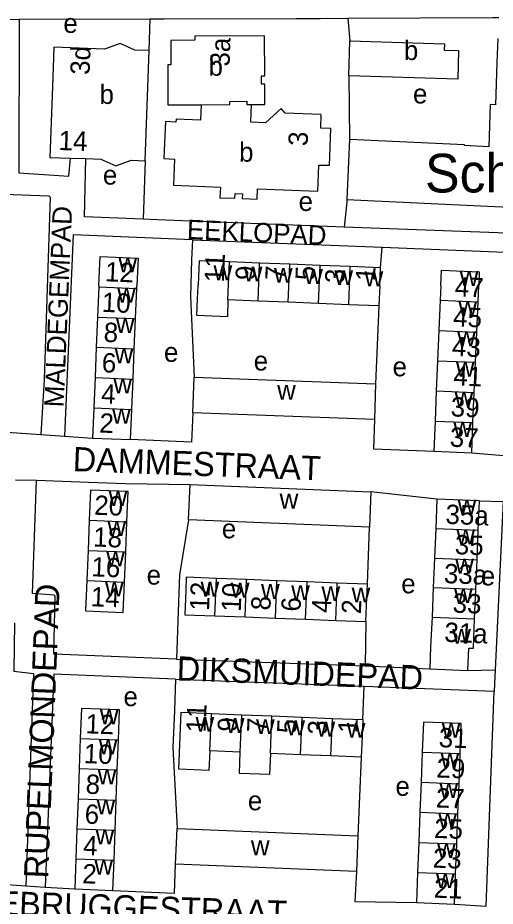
# Model space of a CAD drawing. Extents: x 159675 to 162108, y 386471 to 388472.
# Drawn here: x 161157.6 to 161256.3, y 387621.6 to 387805.3 of the extents above; entities that cross this region are included whole.
import ezdxf

# ---------------------------------------------------------------- set-up
doc = ezdxf.new("R2010")
doc.units = 0
for name, color, linetype in [('BLT_Basislijn', 7, 'Continuous'), ('BLT_Bebouwing', 7, 'Continuous'), ('BLT_Bebouwing_beschrifting', 7, 'Continuous'), ('BLT_Centroide', 7, 'Continuous'), ('BLT_Huisnummer', 7, 'Continuous'), ('BLT_Huisnummer_ tussenligend', 7, 'Continuous'), ('BLT_Huisnummer_reeks', 7, 'Continuous'), ('BLT_Onderverdeling_panden', 7, 'Continuous'), ('BLT_Straatnaam', 7, 'Continuous'), ('BLT_Straatnaam_verkleind', 7, 'Continuous')]:
    doc.layers.add(name, color=color, linetype=linetype)

msp = doc.modelspace()

# ---------------------------------------------------------------- linework, layer by layer
at = {"layer": 'BLT_Basislijn'}
for p, q in [((161157.89, 387804.95), (161152.15, 387804.93)), ((161184.98, 387805.06), (161157.89, 387804.95)), ((161184.77, 387798.54), (161184.98, 387805.06)), ((161225.84, 387805.18), (161220.1, 387805.13)), ((161225.84, 387805.18), (161226.26, 387800.55)), ((161226.06, 387793.34), (161226.2, 387780.16)), ((161183.97, 387775.78), (161183.53, 387763.68)), ((161269.96, 387760.39), (161225.06, 387762.07)), ((161193.74, 387759.43), (161232.92, 387757.9)), ((161232.56, 387753.63), (161232.92, 387757.9)), ((161232.92, 387757.9), (161259.97, 387756.83)), ((161232.25, 387745.77), (161231.57, 387729.68)), ((161153.1, 387719.82), (161162.41, 387719.17)), ((161162.41, 387719.17), (161167.29, 387718.83)), ((161167.29, 387718.83), (161173.07, 387718.43)), ((161157.17, 387709.83), (161161.52, 387709.74)), ((161244.23, 387705.84), (161230.61, 387707.33)), ((161229.88, 387688.22), (161230.33, 387700.04)), ((161229.58, 387680.49), (161229.39, 387671.34)), ((161190.41, 387672.72), (161229.39, 387671.34)), ((161229.39, 387671.34), (161242.75, 387670.73)), ((161250.62, 387670.41), (161256.25, 387670.49)), ((161256.25, 387670.49), (161256.06, 387666.14)), ((161190.19, 387668.6), (161229.18, 387667.17)), ((161228.9, 387660.23), (161229.18, 387667.17)), ((161229.18, 387667.17), (161256.06, 387666.14)), ((161228.58, 387652.46), (161227.88, 387636.23)), ((161149.47, 387626.55), (161159.31, 387625.89)), ((161159.31, 387625.89), (161163.27, 387625.62)), ((161163.27, 387625.62), (161169.41, 387625.21))]:
    msp.add_line(p, q, dxfattribs=at)
for points in [[(161157.89, 387804.95), (161157.83, 387773.27), (161168.2, 387772.6), (161168.51, 387776.32)], [(161220.1, 387805.13), (161219.63, 387805.13), (161215.14, 387805.11), (161187.9, 387805.07), (161184.98, 387805.06)], [(161257.04, 387805.3), (161255.77, 387805.3), (161225.84, 387805.18)], [(161183.53, 387763.68), (161171.41, 387764.2), (161171.68, 387776.21)], [(161125.28, 387769.96), (161164.04, 387768.55), (161164.3, 387768.27), (161163.08, 387730.58), (161162.41, 387719.17)], [(161225.63, 387767.73), (161225.6, 387767.23), (161225.06, 387762.07)], [(161225.06, 387762.07), (161186.45, 387763.55), (161183.53, 387763.68)], [(161193.74, 387759.43), (161169.09, 387760.48), (161167.29, 387718.83)], [(161193.74, 387759.43), (161193.54, 387755.28), (161193.3, 387747.64), (161194.06, 387731.05)], [(161251.43, 387715.39), (161258.08, 387714.85), (161258.61, 387722.94), (161259.97, 387756.83)], [(161193.77, 387723.68), (161193.51, 387717.61), (161180.92, 387718.11)], [(161231.32, 387722.27), (161231.13, 387716.18), (161243.57, 387715.72)], [(161190.41, 387672.72), (161165.11, 387673.79), (161165.36, 387685.72), (161165.17, 387685.99), (161160.64, 387686.31), (161161.52, 387709.74)], [(161161.52, 387709.74), (161172.26, 387709.3), (161179.86, 387709.07), (161193.23, 387708.84)], [(161253.03, 387705.48), (161257.9, 387705.31), (161256.25, 387670.49)], [(161192.92, 387701.54), (161191.03, 387690.16), (161190.75, 387682.56), (161190.41, 387672.72)], [(161156.94, 387680.23), (161156.8, 387670.24), (161160.89, 387669.76), (161159.31, 387625.89)], [(161190.19, 387668.6), (161165.11, 387669.62), (161163.27, 387625.62)], [(161190.19, 387668.6), (161190.02, 387662.14), (161189.65, 387654.43), (161190.53, 387637.75)], [(161247.84, 387622.1), (161254.42, 387621.69), (161256.06, 387666.14)], [(161177.29, 387624.92), (161189.99, 387624.37), (161190.24, 387630.36)], [(161227.59, 387628.8), (161227.29, 387622.6), (161239.99, 387622.41)]]:
    msp.add_lwpolyline(points, dxfattribs=at)
at = {"layer": 'BLT_Bebouwing'}
for p, q in [((161183.97, 387775.78), (161184.77, 387798.54)), ((161195.53, 387787.36), (161195.4, 387784.14)), ((161168.51, 387776.32), (161171.68, 387776.21)), ((161207.59, 387754.62), (161201.35, 387754.86)), ((161213.83, 387754.37), (161207.59, 387754.62)), ((161220.08, 387754.12), (161213.83, 387754.37)), ((161226.32, 387753.88), (161220.08, 387754.12)), ((161232.56, 387753.63), (161226.32, 387753.88)), ((161232.41, 387750), (161232.56, 387753.63)), ((161174.37, 387749.72), (161174.11, 387743.46)), ((161174.38, 387750), (161174.37, 387749.72)), ((161181.97, 387743.13), (161182.23, 387749.39)), ((161182.23, 387749.39), (161182.25, 387750)), ((161245.02, 387750), (161244.89, 387746.92)), ((161252.74, 387746.59), (161252.88, 387750)), ((161207.28, 387746.75), (161201.04, 387747)), ((161213.52, 387746.51), (161207.28, 387746.75)), ((161219.77, 387746.26), (161213.52, 387746.51)), ((161226.01, 387746.01), (161219.77, 387746.26)), ((161232.25, 387745.77), (161226.01, 387746.01)), ((161244.89, 387746.92), (161244.62, 387740.68)), ((161252.48, 387740.35), (161252.74, 387746.59)), ((161174.11, 387743.46), (161173.85, 387737.2)), ((161181.71, 387736.88), (161181.97, 387743.13)), ((161244.62, 387740.68), (161244.36, 387734.44)), ((161252.21, 387734.11), (161252.48, 387740.35)), ((161173.85, 387737.2), (161173.59, 387730.95)), ((161181.45, 387730.62), (161181.71, 387736.88)), ((161244.36, 387734.44), (161244.1, 387728.2)), ((161251.95, 387727.87), (161252.21, 387734.11)), ((161173.59, 387730.95), (161173.33, 387724.69)), ((161181.18, 387724.36), (161181.45, 387730.62)), ((161193.77, 387723.68), (161194.06, 387731.05)), ((161194.06, 387731.05), (161231.57, 387729.68)), ((161231.57, 387729.68), (161231.32, 387722.27)), ((161244.1, 387728.2), (161243.84, 387721.96)), ((161251.69, 387721.63), (161251.95, 387727.87)), ((161173.33, 387724.69), (161173.07, 387718.43)), ((161180.92, 387718.11), (161181.18, 387724.36)), ((161231.32, 387722.27), (161193.77, 387723.68)), ((161243.84, 387721.96), (161243.57, 387715.72)), ((161251.43, 387715.39), (161251.69, 387721.63)), ((161173.07, 387718.43), (161180.92, 387718.11)), ((161243.57, 387715.72), (161251.43, 387715.39)), ((161192.92, 387701.54), (161193.23, 387708.84)), ((161193.23, 387708.84), (161230.61, 387707.33)), ((161230.61, 387707.33), (161230.33, 387700.04)), ((161244.23, 387705.84), (161243.99, 387699.74)), ((161253.03, 387705.48), (161244.23, 387705.84)), ((161252.78, 387699.38), (161253.03, 387705.48)), ((161172.39, 387701.45), (161172.14, 387695.21)), ((161179.93, 387694.9), (161180.18, 387701.14)), ((161230.33, 387700.04), (161192.92, 387701.54)), ((161243.99, 387699.74), (161243.74, 387693.64)), ((161252.53, 387693.28), (161252.78, 387699.38)), ((161172.14, 387695.21), (161171.89, 387688.96)), ((161179.68, 387688.65), (161179.93, 387694.9)), ((161243.74, 387693.64), (161243.49, 387687.54)), ((161252.28, 387687.18), (161252.53, 387693.28)), ((161204.92, 387689.18), (161198.67, 387689.42)), ((161211.16, 387688.94), (161204.92, 387689.18)), ((161217.4, 387688.7), (161211.16, 387688.94)), ((161223.64, 387688.46), (161217.4, 387688.7)), ((161229.88, 387688.22), (161223.64, 387688.46)), ((161243.49, 387687.54), (161243.24, 387681.44)), ((161252.03, 387681.08), (161252.28, 387687.18)), ((161198.38, 387681.68), (161204.62, 387681.45)), ((161204.62, 387681.45), (161210.86, 387681.21)), ((161210.86, 387681.21), (161217.1, 387680.97)), ((161217.1, 387680.97), (161223.34, 387680.73)), ((161223.34, 387680.73), (161229.58, 387680.49)), ((161197.65, 387661.5), (161203.9, 387661.25)), ((161203.9, 387661.25), (161210.15, 387660.99)), ((161210.15, 387660.99), (161216.4, 387660.74)), ((161216.4, 387660.74), (161222.65, 387660.48)), ((161222.65, 387660.48), (161228.9, 387660.23)), ((161170.54, 387656.33), (161170.31, 387650.1)), ((161178.19, 387649.82), (161178.42, 387656.04)), ((161203.58, 387653.48), (161197.33, 387653.74)), ((161241.2, 387653.5), (161240.96, 387647.29)), ((161216.08, 387652.97), (161209.83, 387653.23)), ((161222.33, 387652.71), (161216.08, 387652.97)), ((161228.58, 387652.46), (161222.33, 387652.71)), ((161248.8, 387646.98), (161249.04, 387653.2)), ((161170.31, 387650.1), (161170.09, 387643.88)), ((161177.97, 387643.59), (161178.19, 387649.82)), ((161240.96, 387647.29), (161240.71, 387641.07)), ((161248.56, 387640.76), (161248.8, 387646.98)), ((161170.09, 387643.88), (161169.86, 387637.66)), ((161177.74, 387637.37), (161177.97, 387643.59)), ((161240.71, 387641.07), (161240.47, 387634.85)), ((161248.32, 387634.54), (161248.56, 387640.76)), ((161169.86, 387637.66), (161169.64, 387631.43)), ((161177.52, 387631.15), (161177.74, 387637.37)), ((161190.24, 387630.36), (161190.53, 387637.75)), ((161190.53, 387637.75), (161227.88, 387636.23)), ((161227.88, 387636.23), (161227.59, 387628.8)), ((161240.47, 387634.85), (161240.23, 387628.63)), ((161248.08, 387628.32), (161248.32, 387634.54)), ((161169.64, 387631.43), (161169.41, 387625.21)), ((161177.29, 387624.92), (161177.52, 387631.15)), ((161227.59, 387628.8), (161190.24, 387630.36)), ((161240.23, 387628.63), (161239.99, 387622.41)), ((161247.84, 387622.1), (161248.08, 387628.32)), ((161169.41, 387625.21), (161177.29, 387624.92)), ((161239.99, 387622.41), (161247.84, 387622.1))]:
    msp.add_line(p, q, dxfattribs=at)
for points in [[(161205.92, 387787.41), (161208.7, 387787.41), (161208.68, 387791.59), (161207.98, 387791.59), (161207.97, 387793.35), (161208.67, 387793.36), (161208.64, 387801.62), (161194.24, 387801.54), (161194.22, 387800.68), (161189.28, 387800.64), (161189.28, 387795.59), (161188.62, 387795.58), (161188.65, 387787.34), (161195.53, 387787.36)], [(161226.06, 387793.34), (161226.26, 387800.55)], [(161226.26, 387800.55), (161245.8, 387799.93), (161245.76, 387798.65), (161248.73, 387798.55), (161248.55, 387792.64), (161226.06, 387793.34)], [(161256.82, 387801.08), (161256.64, 387796.09), (161256.31, 387787.34), (161255.27, 387787.38), (161254.95, 387778.68), (161249.95, 387778.91), (161249.96, 387779.07), (161226.2, 387780.16)], [(161184.77, 387798.54), (161181.82, 387798.64), (161178.79, 387800.03), (161175.54, 387798.86), (161165.08, 387799.23), (161164.93, 387795.02), (161164.71, 387789.26), (161164.26, 387776.47), (161168.51, 387776.32)], [(161220.27, 387785.31), (161212.89, 387785.63), (161212.08, 387786.58), (161208.83, 387783.6), (161205.81, 387783.72), (161205.92, 387787.41)], [(161195.4, 387784.14), (161190.37, 387784.34), (161190.32, 387783.76), (161188.15, 387783.88), (161187.9, 387777.87), (161187.83, 387776.21), (161190.02, 387776.11), (161189.79, 387770.73), (161199.5, 387770.32), (161199.4, 387768.14), (161202.46, 387768.01), (161202.54, 387768.99), (161204.06, 387768.92), (161204, 387767.95), (161207.08, 387767.82), (161207.18, 387769.99), (161219.6, 387769.52), (161219.83, 387774.88), (161222.02, 387774.83), (161222.1, 387776.66), (161222.34, 387782.48)], [(161220.27, 387785.31), (161220.15, 387782.57), (161222.34, 387782.48)], [(161226.2, 387780.16), (161225.63, 387767.73)], [(161171.68, 387776.21), (161174.76, 387776.1), (161177.88, 387774.72), (161181.03, 387775.89), (161183.97, 387775.78)], [(161225.63, 387767.73), (161254.7, 387766.41), (161269.97, 387765.71)], [(161174.38, 387750), (161174.63, 387755.98), (161182.49, 387755.65), (161182.25, 387750)], [(161201.35, 387754.86), (161195.11, 387755.11), (161194.91, 387750.12), (161194.91, 387750)], [(161245.02, 387750), (161245.15, 387753.16), (161253, 387752.83), (161252.88, 387750)], [(161201.04, 387747), (161200.98, 387743.5), (161194.66, 387743.75), (161194.8, 387747.25), (161194.91, 387750)], [(161232.41, 387750), (161232.36, 387748.63), (161232.25, 387745.77)], [(161180.18, 387701.14), (161180.43, 387707.39), (161172.64, 387707.7), (161172.39, 387701.45)], [(161171.89, 387688.96), (161171.64, 387682.71), (161179.43, 387682.4), (161179.68, 387688.65)], [(161198.67, 387689.42), (161192.43, 387689.65), (161192.33, 387686.92), (161192.14, 387681.92), (161198.38, 387681.68)], [(161229.58, 387680.49), (161229.77, 387685.49), (161229.88, 387688.22)], [(161243.24, 387681.44), (161242.93, 387675.34), (161242.75, 387670.73)], [(161250.62, 387670.41), (161250.81, 387675.02), (161251.79, 387674.98), (161252.03, 387681.08)], [(161242.75, 387670.73), (161250.62, 387670.41)], [(161178.42, 387656.04), (161178.65, 387662.26), (161170.77, 387662.55), (161170.54, 387656.33)], [(161197.33, 387653.74), (161197.13, 387649.71), (161190.92, 387649.97), (161191.19, 387656.76), (161191.4, 387661.76), (161197.65, 387661.5)], [(161228.9, 387660.23), (161228.69, 387655.23), (161228.58, 387652.46)], [(161249.04, 387653.2), (161249.28, 387659.42), (161241.44, 387659.72), (161241.2, 387653.5)], [(161209.83, 387653.23), (161209.65, 387648.85), (161203.44, 387649.11), (161203.58, 387653.48)]]:
    msp.add_lwpolyline(points, dxfattribs=at)
at = {"layer": 'BLT_Onderverdeling_panden'}
for p, q in [((161195.53, 387787.36), (161201.42, 387787.39)), ((161201.04, 387747), (161201.35, 387754.86)), ((161207.28, 387746.75), (161207.59, 387754.62)), ((161213.52, 387746.51), (161213.83, 387754.37)), ((161219.77, 387746.26), (161220.08, 387754.12)), ((161226.01, 387746.01), (161226.32, 387753.88)), ((161174.37, 387749.72), (161182.23, 387749.39)), ((161244.89, 387746.92), (161252.74, 387746.59)), ((161174.11, 387743.46), (161181.97, 387743.13)), ((161244.62, 387740.68), (161252.48, 387740.35)), ((161173.85, 387737.2), (161181.71, 387736.88)), ((161244.36, 387734.44), (161252.21, 387734.11)), ((161173.59, 387730.95), (161181.45, 387730.62)), ((161244.1, 387728.2), (161251.95, 387727.87)), ((161173.33, 387724.69), (161181.18, 387724.36)), ((161243.84, 387721.96), (161251.69, 387721.63)), ((161172.39, 387701.45), (161180.18, 387701.14)), ((161243.99, 387699.74), (161252.78, 387699.38)), ((161172.14, 387695.21), (161179.93, 387694.9)), ((161243.74, 387693.64), (161252.53, 387693.28)), ((161171.89, 387688.96), (161179.68, 387688.65)), ((161198.38, 387681.68), (161198.67, 387689.42)), ((161204.62, 387681.45), (161204.92, 387689.18)), ((161210.86, 387681.21), (161211.16, 387688.94)), ((161217.1, 387680.97), (161217.4, 387688.7)), ((161223.34, 387680.73), (161223.64, 387688.46)), ((161243.49, 387687.54), (161252.28, 387687.18)), ((161243.24, 387681.44), (161252.03, 387681.08)), ((161197.33, 387653.74), (161197.65, 387661.5)), ((161203.58, 387653.48), (161203.9, 387661.25)), ((161209.83, 387653.23), (161210.15, 387660.99)), ((161216.08, 387652.97), (161216.4, 387660.74)), ((161222.33, 387652.71), (161222.65, 387660.48)), ((161170.54, 387656.33), (161178.42, 387656.04)), ((161241.2, 387653.5), (161249.04, 387653.2)), ((161170.31, 387650.1), (161178.19, 387649.82)), ((161240.96, 387647.29), (161248.8, 387646.98)), ((161170.09, 387643.88), (161177.97, 387643.59)), ((161240.71, 387641.07), (161248.56, 387640.76)), ((161169.86, 387637.66), (161177.74, 387637.37)), ((161240.47, 387634.85), (161248.32, 387634.54)), ((161169.64, 387631.43), (161177.52, 387631.15)), ((161240.23, 387628.63), (161248.08, 387628.32))]:
    msp.add_line(p, q, dxfattribs=at)
msp.add_lwpolyline([(161201.42, 387787.39), (161201.42, 387788.05), (161204.93, 387788.06), (161204.94, 387787.4), (161205.92, 387787.41)], dxfattribs=at)

# ---------------------------------------------------------------- texts
at = {"layer": 'BLT_Bebouwing_beschrifting'}
msp.add_text('School', height=8, dxfattribs=at).set_placement((161241.78, 387769.22))
at = {"layer": 'BLT_Centroide'}
for s, p in [('e', (161167.05, 387802.21)), ('b', (161237.41, 387796.59)), ('b', (161197.05, 387793.34)), ('b', (161174.52, 387787.52)), ('e', (161239.29, 387787.62)), ('b', (161203.36, 387775.58)), ('e', (161175.22, 387770.84)), ('e', (161215.66, 387765.39)), ('w', (161178.43, 387752.69)), ('w', (161198.08, 387751.06)), ('w', (161204.31, 387750.81)), ('w', (161210.56, 387750.56)), ('w', (161216.8, 387750.31)), ('w', (161223.05, 387750.06)), ('w', (161229.28, 387749.81)), ('w', (161248.95, 387749.88)), ('w', (161178.17, 387746.44)), ('w', (161248.68, 387743.62)), ('w', (161177.91, 387740.16)), ('w', (161248.42, 387737.41)), ('w', (161177.65, 387733.91)), ('e', (161187.84, 387734.2)), ('e', (161206.38, 387732.41)), ('e', (161235.08, 387731.21)), ('w', (161248.16, 387731.16)), ('w', (161177.39, 387727.66)), ('w', (161211.22, 387726.37)), ('w', (161247.89, 387724.91)), ('w', (161177.12, 387721.41)), ('w', (161247.63, 387718.69)), ('w', (161176.41, 387704.41)), ('w', (161211.74, 387703.84)), ('w', (161248.51, 387702.62)), ('w', (161176.16, 387698.19)), ('e', (161199.8, 387697.71)), ('w', (161248.26, 387696.5)), ('w', (161175.91, 387691.94)), ('w', (161248.01, 387690.41)), ('e', (161184.26, 387688.14)), ('e', (161253.3, 387687.96)), ('w', (161175.66, 387685.69)), ('w', (161195.41, 387685.67)), ('w', (161201.64, 387685.44)), ('w', (161207.89, 387685.19)), ('e', (161236.87, 387686.34)), ('w', (161214.12, 387684.95)), ('w', (161220.38, 387684.72)), ('w', (161226.61, 387684.47)), ('w', (161247.77, 387684.31)), ('w', (161247.39, 387675.91)), ('e', (161179.47, 387663.01)), ('w', (161174.59, 387659.28)), ('w', (161194.36, 387657.73)), ('w', (161200.61, 387657.48)), ('w', (161206.86, 387657.23)), ('w', (161213.11, 387656.98)), ('w', (161219.36, 387656.73)), ('w', (161225.61, 387656.48)), ('w', (161245.24, 387656.47)), ('w', (161174.37, 387653.06)), ('w', (161244.99, 387650.25)), ('w', (161174.15, 387646.84)), ('e', (161235.67, 387644.47)), ('w', (161244.76, 387644.03)), ('e', (161205.18, 387641.48)), ('w', (161173.91, 387640.62)), ('w', (161244.52, 387637.81)), ('w', (161173.7, 387634.41)), ('w', (161205.8, 387632.19)), ('w', (161244.27, 387631.59)), ('w', (161173.46, 387628.19)), ('w', (161244.04, 387625.38))]:
    msp.add_text(s, height=4, dxfattribs=at).set_placement(p)
at = {"layer": 'BLT_Huisnummer'}
for s, rotation, p in [('3a', 87.9868, (161201.38, 387795.21)), ('3', 87.6141, (161217.51, 387778.75)), ('11', 87.719, (161200.21, 387750.58)), ('12', 357.6162, (161175.6, 387750.86)), ('5', 87.719, (161218.98, 387751)), ('1', 87.719, (161231.45, 387750.81)), ('47', 357.5867, (161247.87, 387747.77)), ('6', 357.6162, (161174.93, 387732.06)), ('41', 357.5867, (161247.57, 387729.36)), ('2', 357.6162, (161174.43, 387719.59)), ('37', 357.5867, (161246.84, 387716.67)), ('20', 357.7217, (161173.38, 387702.6)), ('35a', 357.6685, (161245.95, 387700.72)), ('35', 357.6685, (161247.88, 387694.45)), ('33a', 357.6683, (161245.63, 387688.47)), ('12', 87.8111, (161197.15, 387682.67)), ('14', 357.7217, (161172.65, 387683.68)), ('6', 87.8111, (161216.06, 387682.51)), ('2', 87.8111, (161228.52, 387682.01)), ('33', 357.6683, (161247.43, 387682.38)), ('31a', 357.6685, (161245.71, 387676.33)), ('11', 87.6459, (161196.42, 387657.51)), ('12', 357.9214, (161171.56, 387657.4)), ('5', 87.6459, (161215.18, 387657.31)), ('1', 87.6459, (161227.79, 387657.37)), ('31', 357.7806, (161244.56, 387654.54)), ('6', 357.9214, (161171.4, 387638.73)), ('25', 357.7806, (161243.6, 387635.79)), ('2', 357.9214, (161170.91, 387626.4)), ('21', 357.7806, (161243.54, 387623.43))]:
    msp.add_text(s, height=4, rotation=rotation, dxfattribs=at).set_placement(p)
at = {"layer": 'BLT_Huisnummer_ tussenligend'}
for s, rotation, p in [('9', 87.735, (161206.6, 387751.02)), ('7', 87.7347, (161212.75, 387751.01)), ('3', 87.7344, (161225.09, 387750.39)), ('10', 357.6159, (161174.93, 387744.55)), ('45', 357.594, (161247.52, 387741.56)), ('8', 357.6159, (161175.32, 387738.35)), ('43', 357.5864, (161247.28, 387735.42)), ('4', 357.6156, (161174.8, 387725.61)), ('39', 357.5861, (161247.02, 387722.94)), ('18', 357.7214, (161173.16, 387696.03)), ('16', 357.7214, (161172.79, 387689.87)), ('10', 87.8074, (161203.7, 387682.49)), ('8', 87.8071, (161209.82, 387682.76)), ('4', 87.8071, (161222.35, 387682.24)), ('9', 87.6552, (161202.89, 387657.66)), ('7', 87.6549, (161208.98, 387657.54)), ('3', 87.6546, (161221.52, 387657.04)), ('10', 357.9206, (161171.21, 387651.24)), ('29', 357.7809, (161244.07, 387648.28)), ('8', 357.9206, (161171.6, 387644.92)), ('27', 357.7809, (161243.95, 387642.08)), ('4', 357.9206, (161171.09, 387632.22)), ('23', 357.7806, (161243.33, 387629.64))]:
    msp.add_text(s, height=4, rotation=rotation, dxfattribs=at).set_placement(p)
at = {"layer": 'BLT_Huisnummer_reeks'}
for s, rotation, p in [('3d', 87.7813, (161172.46, 387793.48)), ('14', 357.9926, (161166.02, 387778))]:
    msp.add_text(s, height=4, rotation=rotation, dxfattribs=at).set_placement(p)
at = {"layer": 'BLT_Straatnaam'}
for s, height, rotation, p in [('DAMMESTRAAT', 4.9999, 357.8254, (161168.93, 387711.62)), ('RUPELMONDEPAD', 4.9999, 87.7264, (161163.89, 387627.34)), ('DIKSMUIDEPAD', 5, 357.8251, (161190.41, 387668.34)), ('ZEEBRUGGESTRAAT', 5, 358.0247, (161144.86, 387620.13))]:
    msp.add_text(s, height=height, rotation=rotation, dxfattribs=at).set_placement(p)
at = {"layer": 'BLT_Straatnaam_verkleind'}
for s, height, rotation, p in [('MALDEGEMPAD', 3.9999, 87.5607, (161167.1, 387724.75)), ('EEKLOPAD', 4, 357.4878, (161192.52, 387759.61))]:
    msp.add_text(s, height=height, rotation=rotation, dxfattribs=at).set_placement(p)

doc.saveas('drawing.dxf')
